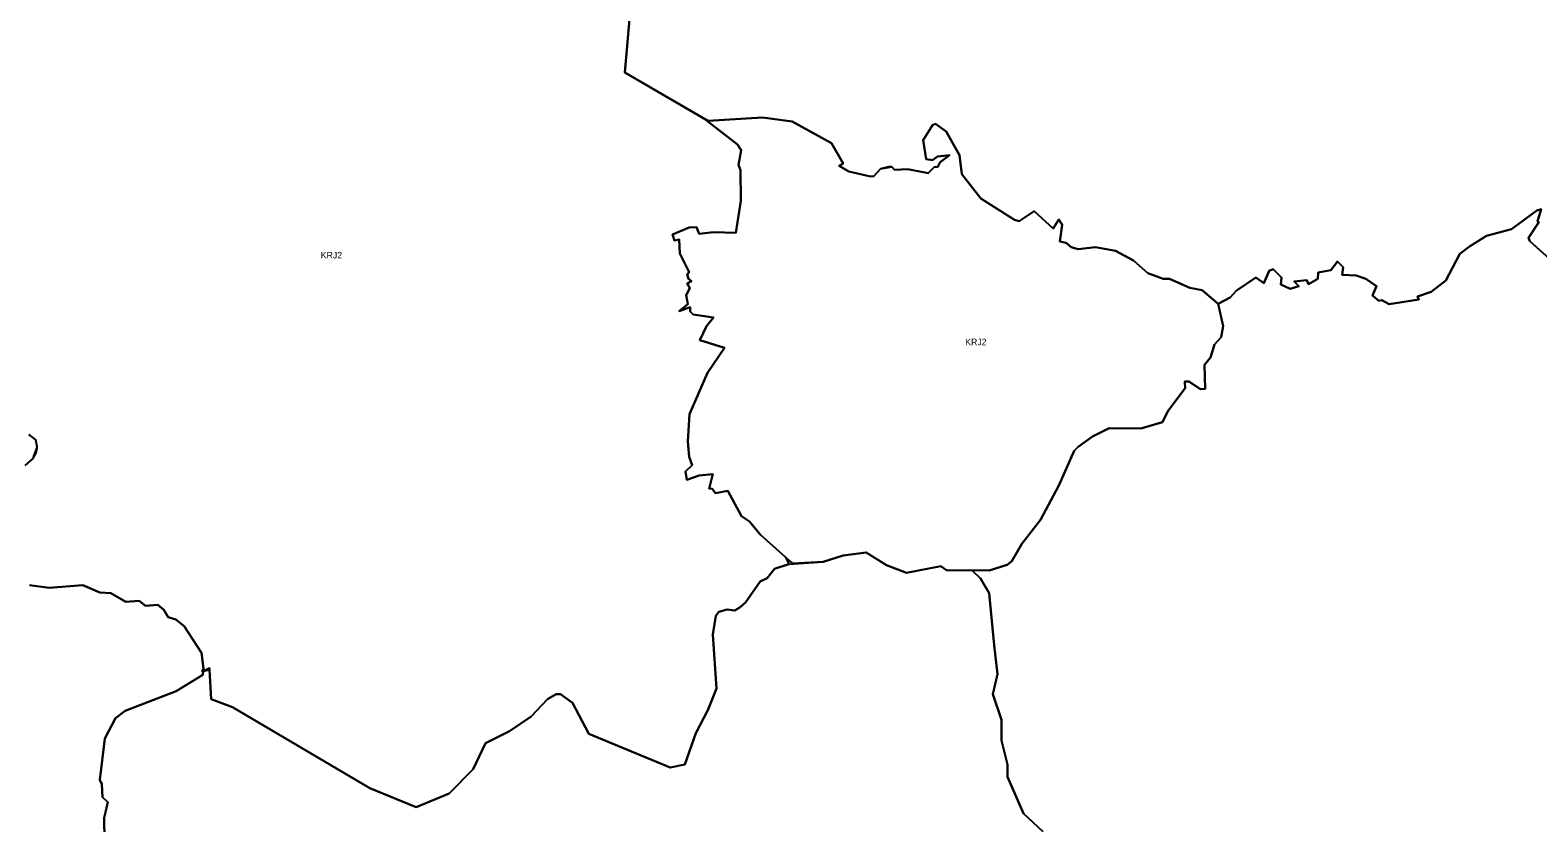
# Model space of a CAD drawing. Extents: x -563112 to -465432, y -1206259 to -1132144.
# Drawn here: x -530418 to -518862, y -1175211 to -1169132 of the extents above; entities that cross this region are included whole.
import ezdxf

# ---------------------------------------------------------------- set-up
doc = ezdxf.new("R2010")
doc.units = 0
doc.layers.add('krajiny', color=7, linetype='Continuous')

msp = doc.modelspace()

# ---------------------------------------------------------------- linework, layer by layer
at = {"layer": 'krajiny'}
for points in [[(-525824.05, -1169049.32), (-525859.21, -1169456.36), (-525246.13, -1169813.71), (-524996.07, -1170008.21), (-524968.68, -1170051.51), (-524989.33, -1170165.61), (-524974.49, -1170206.69), (-524971.47, -1170442.24), (-525009.71, -1170685.76), (-525180.29, -1170680.56), (-525289.23, -1170693.82), (-525310.83, -1170643.44), (-525367.5, -1170645.22), (-525493.62, -1170699.86), (-525479.26, -1170746.2), (-525443.52, -1170737.47), (-525438.76, -1170844.16), (-525367.85, -1170988.82), (-525383.28, -1171005.04), (-525371.96, -1171038.05), (-525348.92, -1171057.55), (-525383.38, -1171075.69), (-525361.53, -1171111.26), (-525389.44, -1171164.78), (-525376.92, -1171233.95), (-525444.46, -1171286.74), (-525359.01, -1171256.07), (-525360.31, -1171290.78), (-525335.69, -1171313.06), (-525179.86, -1171336.42), (-525235.29, -1171402.17), (-525284.78, -1171509.76), (-525096.86, -1171568.5), (-525225.37, -1171760.59), (-525364.79, -1172076.16), (-525376.31, -1172287.52), (-525367.09, -1172404.4), (-525343.53, -1172466.84), (-525396.2, -1172516.18), (-525384.64, -1172581.59), (-525290.69, -1172547.14), (-525186.01, -1172537.83), (-525212.62, -1172646.23), (-525190.18, -1172650.6), (-525166.23, -1172682.42), (-525070.89, -1172663.53), (-524966.85, -1172860.21), (-524903.73, -1172899.3), (-524823.32, -1172999.94), (-524629.35, -1173173.27), (-524603.79, -1173228.16), (-524713, -1173263.1), (-524770.14, -1173335.07), (-524823.43, -1173359.28), (-524935.64, -1173522.07), (-524974.85, -1173556.56), (-525016.84, -1173581.83), (-525075.45, -1173573.62), (-525140.19, -1173591.94), (-525162.39, -1173622.07), (-525185.43, -1173766.98), (-525158.62, -1174180.73), (-525223.73, -1174346.72), (-525315.73, -1174522.56), (-525399.04, -1174762.63), (-525513.24, -1174786.17), (-526135.15, -1174528.06), (-526260.86, -1174289.8), (-526353.48, -1174223.62), (-526386.56, -1174223.62), (-526452.72, -1174263.33), (-526578.43, -1174395.69), (-526743.83, -1174508.2), (-526929.08, -1174600.86), (-527021.7, -1174799.4), (-527206.95, -1174984.71), (-527458.36, -1175090.61), (-527815.63, -1174945), (-528867.58, -1174322.89), (-529031, -1174263.33), (-529043.54, -1174037.49), (-529044.23, -1174025.07), (-529085.13, -1174044.32), (-529100, -1174051.32), (-529088.9, -1174027.93), (-529105.4, -1173907.63), (-529237.61, -1173702.78), (-529300.44, -1173650.92), (-529361.14, -1173632.22), (-529393.77, -1173576.38), (-529438.31, -1173538.45), (-529533.7, -1173545.62), (-529582.59, -1173507.33), (-529684.1, -1173516.07), (-529800.21, -1173448.52), (-529883.46, -1173444.41), (-530014.11, -1173389.02), (-530272.31, -1173407.97), (-530423.14, -1173386.86)], [(-518170.41, -1171427.96), (-518924.22, -1170750.58), (-518932.94, -1170725.63), (-518854.68, -1170605.18), (-518864.14, -1170600), (-518835.63, -1170505.52), (-518870.43, -1170515.2), (-519063.52, -1170658.14), (-519256.45, -1170709.4), (-519385.34, -1170792.03), (-519459.12, -1170848.27), (-519567.94, -1171051.87), (-519679.22, -1171137.6), (-519784.24, -1171175.05), (-519774.82, -1171198.83), (-520002.82, -1171233.75), (-520057.69, -1171202.29), (-520079.8, -1171206.66), (-520130.21, -1171167.58), (-520098.9, -1171095.99), (-520181.16, -1171038.3), (-520254.37, -1171012.73), (-520362.86, -1171009.74), (-520353.41, -1170950.82), (-520397.91, -1170907.19), (-520449.87, -1170972.4), (-520544.74, -1170990.32), (-520548.12, -1171039.04), (-520619.96, -1171080.28), (-520633.04, -1171050.55), (-520729.06, -1171059.88), (-520693.76, -1171095.42), (-520759.88, -1171116.81), (-520832.36, -1171081.48), (-520827.14, -1171028.95), (-520890.28, -1170963.79), (-520920.33, -1170977.46), (-520961.95, -1171072.49), (-521024.45, -1171027.65), (-521175.45, -1171131.94), (-521219.24, -1171181.14), (-521312.43, -1171229.6), (-521435.21, -1171126.81), (-521530.29, -1171107.27), (-521684.96, -1171038.64), (-521733.63, -1171038.53), (-521850.22, -1170995.56), (-521961.27, -1170898.59), (-522099.95, -1170823.5), (-522251.55, -1170795.74), (-522385.2, -1170811.28), (-522439.09, -1170795.99), (-522477.12, -1170762.58), (-522526.79, -1170753.92), (-522507.54, -1170625.5), (-522533.62, -1170583.85), (-522576.09, -1170654.21), (-522722.31, -1170521.01), (-522838.21, -1170597.67), (-522873.02, -1170586.55), (-523131.77, -1170421.92), (-523278.12, -1170236.24), (-523293.87, -1170091.7), (-523397.46, -1169910.51), (-523479.05, -1169851.14), (-523502.55, -1169861.5), (-523573.95, -1169976.66), (-523551.41, -1170121.72), (-523500.73, -1170127.98), (-523462.91, -1170100.64), (-523371.18, -1170090.3), (-523442.84, -1170143.58), (-523459.71, -1170180.37), (-523489.46, -1170182.37), (-523534.56, -1170229.45), (-523690, -1170197.6), (-523792.14, -1170203.63), (-523814.3, -1170179.64), (-523839.87, -1170181), (-523901.51, -1170196.69), (-523950.37, -1170251.09), (-523976.42, -1170255.04), (-524143.69, -1170216.97), (-524216.75, -1170172.7), (-524185.75, -1170154.54), (-524276.83, -1169999.07), (-524578.23, -1169833.24), (-524804.29, -1169803.09), (-525221.23, -1169828.22), (-525859.21, -1169456.36), (-525824.05, -1169049.32)], [(-522655.39, -1175276.77), (-522804.2, -1175137.98), (-522927.92, -1174856.58), (-522925.78, -1174764.39), (-522972.28, -1174579.88), (-522972.48, -1174421.44), (-523038.29, -1174223.59), (-523004.15, -1174069.35), (-523029.52, -1173849.01), (-523067.94, -1173449.28), (-523134.1, -1173336.77), (-523198.06, -1173275.63), (-523393.24, -1173272.97), (-523068.64, -1173274.55), (-522930.44, -1173231.14), (-522893.09, -1173203.74), (-522816.27, -1173070.13), (-522674.85, -1172886.88), (-522533.42, -1172622.83), (-522414.72, -1172358.95), (-522386.29, -1172328.28), (-522274.87, -1172248.11), (-522147.91, -1172185.36), (-521904.51, -1172188), (-521738.37, -1172137.64), (-521697.51, -1172054.87), (-521565.76, -1171877.24), (-521567.13, -1171825.62), (-521537.17, -1171825.91), (-521446.68, -1171884.38), (-521412.69, -1171883.84), (-521416.97, -1171698.49), (-521370.95, -1171641.34), (-521340.03, -1171542.75), (-521289.05, -1171485.85), (-521273.41, -1171403.16), (-521312.43, -1171229.6), (-521219.24, -1171181.14), (-521175.45, -1171131.94), (-521024.45, -1171027.65), (-520961.95, -1171072.49), (-520920.33, -1170977.46), (-520890.28, -1170963.79), (-520827.14, -1171028.95), (-520832.36, -1171081.48), (-520759.88, -1171116.81), (-520693.76, -1171095.42), (-520729.06, -1171059.88), (-520633.04, -1171050.55), (-520619.96, -1171080.28), (-520548.12, -1171039.04), (-520544.74, -1170990.32), (-520449.87, -1170972.4), (-520397.91, -1170907.19), (-520353.41, -1170950.82), (-520362.86, -1171009.74), (-520254.37, -1171012.73), (-520181.16, -1171038.3), (-520098.9, -1171095.99), (-520130.21, -1171167.58), (-520079.8, -1171206.66), (-520057.69, -1171202.29), (-520002.82, -1171233.75), (-519774.82, -1171198.83), (-519784.24, -1171175.05), (-519679.22, -1171137.6), (-519567.94, -1171051.87), (-519459.12, -1170848.27), (-519385.34, -1170792.03), (-519256.45, -1170709.4), (-519063.52, -1170658.14), (-518870.43, -1170515.2), (-518835.63, -1170505.52), (-518864.14, -1170600), (-518854.68, -1170605.18), (-518932.94, -1170725.63), (-518924.22, -1170750.58), (-518170.41, -1171427.96)], [(-530429.22, -1172233.22), (-530376.93, -1172274.82), (-530365.7, -1172324.8), (-530368.04, -1172337.96), (-530374.78, -1172375.91), (-530391.1, -1172406.35), (-530396.76, -1172416.91), (-530459.25, -1172470.54)], [(-530457.15, -1172470.54), (-530394.66, -1172416.91), (-530391.1, -1172406.35), (-530368.04, -1172337.96), (-530363.6, -1172324.8), (-530374.83, -1172274.82), (-530427.12, -1172233.22)], [(-529847.31, -1175345.29), (-529851.84, -1175171.06), (-529822.49, -1175051.92), (-529864.26, -1175014.83), (-529867.86, -1174913.02), (-529882.91, -1174880.22), (-529846.46, -1174562.94), (-529763.75, -1174407.83), (-529689.81, -1174351.73), (-529299.46, -1174200.24), (-529094.76, -1174075.42), (-529091.08, -1174047.58), (-529043.53, -1174037.8), (-529031, -1174263.33), (-528867.58, -1174322.89), (-527815.63, -1174945), (-527458.36, -1175090.61), (-527206.95, -1174984.71), (-527021.7, -1174799.4), (-526929.08, -1174600.86), (-526743.83, -1174508.2), (-526578.43, -1174395.69), (-526452.72, -1174263.33), (-526386.56, -1174223.62), (-526353.48, -1174223.62), (-526260.86, -1174289.8), (-526135.15, -1174528.06), (-525513.24, -1174786.17), (-525399.04, -1174762.63), (-525315.73, -1174522.56), (-525223.73, -1174346.72), (-525158.62, -1174180.73), (-525185.43, -1173766.98), (-525162.39, -1173622.07), (-525140.19, -1173591.94), (-525075.45, -1173573.62), (-525016.84, -1173581.83), (-524974.85, -1173556.56), (-524935.64, -1173522.07), (-524823.43, -1173359.28), (-524770.14, -1173335.07), (-524713, -1173263.1), (-524603.79, -1173228.16), (-524340.5, -1173209.94), (-524187.72, -1173160.34), (-524010.02, -1173138.7), (-523854.88, -1173234.01), (-523700.27, -1173294), (-523437.79, -1173242.08), (-523393.24, -1173272.97), (-523198.06, -1173275.63), (-523134.1, -1173336.77), (-523067.94, -1173449.28), (-523029.52, -1173849.01), (-523004.15, -1174069.35), (-523038.29, -1174223.59), (-522972.48, -1174421.44), (-522972.28, -1174579.88), (-522925.78, -1174764.39), (-522927.92, -1174856.58), (-522804.2, -1175137.98), (-522655.39, -1175276.77)], [(-530423.14, -1173386.86), (-530272.31, -1173407.97), (-530014.11, -1173389.02), (-529883.46, -1173444.41), (-529800.21, -1173448.52), (-529684.1, -1173516.07), (-529582.59, -1173507.33), (-529533.7, -1173545.62), (-529438.31, -1173538.45), (-529393.77, -1173576.38), (-529361.14, -1173632.22), (-529300.44, -1173650.92), (-529237.61, -1173702.78), (-529105.4, -1173907.63), (-529088.9, -1174027.93), (-529100, -1174051.32), (-529085.13, -1174044.32), (-529044.23, -1174025.07), (-529043.55, -1174037.49), (-529043.53, -1174037.8), (-529091.08, -1174047.58), (-529094.76, -1174075.42), (-529299.46, -1174200.24), (-529689.81, -1174351.73), (-529763.75, -1174407.83), (-529846.46, -1174562.94), (-529882.91, -1174880.22), (-529867.86, -1174913.02), (-529864.26, -1175014.83), (-529822.49, -1175051.92), (-529851.84, -1175171.06), (-529847.31, -1175345.29)]]:
    msp.add_lwpolyline(points, dxfattribs=at)
for points in [[(-524804.29, -1169803.09), (-524578.23, -1169833.24), (-524276.83, -1169999.07), (-524185.75, -1170154.54), (-524216.75, -1170172.7), (-524143.69, -1170216.97), (-523976.42, -1170255.04), (-523950.37, -1170251.09), (-523901.51, -1170196.69), (-523814.3, -1170179.64), (-523792.14, -1170203.63), (-523690, -1170197.6), (-523534.56, -1170229.45), (-523489.46, -1170182.37), (-523459.71, -1170180.37), (-523442.84, -1170143.58), (-523371.18, -1170090.3), (-523462.91, -1170100.64), (-523500.73, -1170127.98), (-523551.41, -1170121.72), (-523573.95, -1169976.66), (-523502.55, -1169861.5), (-523479.05, -1169851.14), (-523397.46, -1169910.51), (-523293.87, -1170091.7), (-523278.12, -1170236.24), (-523131.77, -1170421.92), (-522873.02, -1170586.55), (-522838.21, -1170597.67), (-522722.31, -1170521.01), (-522576.09, -1170654.21), (-522533.62, -1170583.85), (-522507.54, -1170625.5), (-522526.79, -1170753.92), (-522477.12, -1170762.58), (-522439.09, -1170795.99), (-522385.2, -1170811.28), (-522251.55, -1170795.74), (-522099.95, -1170823.5), (-521961.27, -1170898.59), (-521850.22, -1170995.56), (-521733.63, -1171038.53), (-521684.96, -1171038.64), (-521530.29, -1171107.27), (-521435.21, -1171126.81), (-521312.43, -1171229.6), (-521273.41, -1171403.16), (-521289.05, -1171485.85), (-521340.03, -1171542.75), (-521370.95, -1171641.34), (-521416.97, -1171698.49), (-521412.69, -1171883.84), (-521446.68, -1171884.38), (-521537.17, -1171825.91), (-521567.13, -1171825.62), (-521565.76, -1171877.24), (-521697.51, -1172054.87), (-521738.37, -1172137.64), (-521904.51, -1172188), (-522147.91, -1172185.36), (-522274.87, -1172248.11), (-522386.29, -1172328.28), (-522414.72, -1172358.95), (-522533.42, -1172622.83), (-522674.85, -1172886.88), (-522816.27, -1173070.13), (-522893.09, -1173203.74), (-522930.44, -1173231.14), (-523068.64, -1173274.55), (-523393.24, -1173272.97), (-523437.79, -1173242.08), (-523700.27, -1173294), (-523854.88, -1173234.01), (-524010.02, -1173138.7), (-524187.72, -1173160.34), (-524340.5, -1173209.94), (-524573.56, -1173223.13), (-524629.35, -1173173.28), (-524823.32, -1172999.94), (-524903.73, -1172899.3), (-524966.85, -1172860.21), (-525070.89, -1172663.53), (-525166.23, -1172682.42), (-525190.18, -1172650.6), (-525212.62, -1172646.23), (-525186.01, -1172537.83), (-525290.69, -1172547.14), (-525384.64, -1172581.59), (-525396.2, -1172516.18), (-525343.53, -1172466.84), (-525367.09, -1172404.4), (-525376.31, -1172287.52), (-525364.79, -1172076.16), (-525225.37, -1171760.59), (-525096.86, -1171568.5), (-525284.78, -1171509.76), (-525235.29, -1171402.17), (-525179.86, -1171336.42), (-525335.69, -1171313.06), (-525360.31, -1171290.78), (-525359.01, -1171256.07), (-525444.46, -1171286.74), (-525376.92, -1171233.95), (-525389.44, -1171164.78), (-525361.53, -1171111.26), (-525383.38, -1171075.69), (-525348.92, -1171057.55), (-525371.96, -1171038.05), (-525383.28, -1171005.04), (-525367.85, -1170988.82), (-525438.76, -1170844.16), (-525443.52, -1170737.47), (-525479.26, -1170746.2), (-525493.62, -1170699.86), (-525367.5, -1170645.22), (-525310.83, -1170643.44), (-525289.23, -1170693.82), (-525180.29, -1170680.56), (-525009.71, -1170685.76), (-524971.47, -1170442.24), (-524974.49, -1170206.69), (-524989.33, -1170165.61), (-524968.68, -1170051.51), (-524996.07, -1170008.21), (-525246.13, -1169813.71), (-525221.23, -1169828.22)], [(-529043.54, -1174037.49), (-529085.13, -1174044.32), (-529044.23, -1174025.07)]]:
    msp.add_lwpolyline(points, close=True, dxfattribs=at)

# ---------------------------------------------------------------- texts
for p in [(-528190.4, -1170882.58), (-523251.27, -1171548.54)]:
    msp.add_text('KRJ2', height=50, dxfattribs=at).set_placement(p)

doc.saveas('drawing.dxf')
